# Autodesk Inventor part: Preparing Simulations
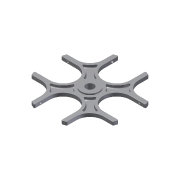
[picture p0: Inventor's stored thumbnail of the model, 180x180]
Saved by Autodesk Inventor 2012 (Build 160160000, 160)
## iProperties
Created: 2004-06
Part Number: Preparing Simulations
Document SubType Name: Modeling
Designer: brent
Manufacturer: Standard
Standards Organization: Custom
Density: 1 g/cm^3
Material: Default
Mass: 73.4254 g
Surface Area: 338.43 cm^2
Volume: 73.4254 cm^3
Author: Autodesk, Inc.
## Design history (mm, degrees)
sketch "Sketch1"
  geometry: C1 r 100 at (0, 0)
  constraints: 1 centre point
  dimensions: "d0" = 200 diameter of C1
extrude "Extrusion1" new body sketch "Sketch1" stored distance "d1" = 8; taper "d2" = 0 deg
sketch "Sketch2"
  geometry: L1 (-30, 95.394)-(-30, 60.394); L2 (30, 60.394)-(30, 95.394); A1 r 100 centre (0, 0) between (-30, 95.394) and (30, 95.394) reference; A2 r 30 centre (0, 60.394) between (-30, 60.394) and (30, 60.394)
  constraints: 4 end point, 4 point on circle, 2 tangent, 1 centre point, 1 parallel, 1 vertical, 1 vertical alignment
  dimensions: "d3" = 60 distance between parallel lines of L2 L1; "d4" = 35 distance of L2.start L2.end
extrude "Extrusion2" cut sketch "Sketch2" stored distance "d5" = 8; taper "d6" = 0 deg
sketch "Sketch5"
  geometry: L1 (0, 35)-(8, 35) reference; L2 (0, 0)-(8, 0) reference; L3 (0, -30.394)-(0, 35) reference; 2 further points
  constraints: 1 midpoint, 1 vertical alignment
  dimensions: "d30" = 20 distance from line of L2 point (4, 20)
hole "Hole2" sketch "Sketch5" at (4, 20) diameter "d31" = 5; stored, may be unused: countersink angle "d35" = 90 deg, drill point angle "d37" = 118 deg; dims "d32" = 6, "d33" = 4, "d34" = 2, "d36" = 5
mirror "Mirror1"
pattern_circular "Circular Pattern2" dims "d39" = 360 deg
sketch "Sketch7"
  geometry: L1 (-30, 60.394)-(-30, 95.394) reference; L2 (-95.394, 30)-(-60.394, 30) reference; L3 (-40, 91.652)-(-40, 70); L4 (-70, 40)-(-91.652, 40); A1 r 100 centre (0, 0) between (-30, 95.394) and (-95.394, 30) reference; A2 r 30 centre (-70, 70) between (-70, 40) and (-40, 70)
  constraints: 4 end point, 4 point on circle, 2 tangent, 1 centre point
  dimensions: "d41" = 10 distance between parallel lines of L1 L3 (= d42); "d42" = 10 distance between parallel lines of L2 L4; "d43" = 30 radius of A2
extrude "Extrusion5" cut sketch "Sketch7" stored distance "d44" = 6; taper "d45" = 0 deg
pattern_circular "Circular Pattern3" dims angle "d47" = 360 deg
sketch "Sketch4"
  geometry: C1 r 20 at (0, 0); A1 r 100 centre (0, 0) between (95.394, 30) and (30, 95.394) reference
  constraints: 1 centre point, 1 coincident
  dimensions: "d13" = 40 diameter of C1
extrude "Extrusion4" join sketch "Sketch4" stored distance "d14" = 14; taper "d15" = 0 deg
hole "Hole1" diameter "d18" = 18; stored, may be unused: countersink angle "d22" = 90 deg, drill point angle "d24" = 118 deg; dims "d16" = 10, "d17" = 10, "d19" = 6, "d20" = 4, "d21" = 2, "d23" = 8
sketch "Sketch8"
  geometry: C1 r 20 at (0, 0) reference; A1 r 30 centre (0, 60.394) between (-30, 60.394) and (30, 60.394) reference; A2 r 30 centre (-70, 70) between (-70, 40) and (-40, 70) reference; A3 r 30 centre (-60.394, 0) between (-60.394, -30) and (-60.394, 30) reference; A4 r 100 centre (0, 0) between (95.394, 30) and (91.652, 40) reference; A5 r 36 centre (0, 60.394) between (-35.941, 58.338) and (-6.913, 25.064); A6 r 36 centre (-70, 70) between (-58.338, 35.941) and (-35.941, 58.338); A7 r 36 centre (-60.394, 0) between (-25.064, 6.913) and (-58.338, 35.941); A8 r 26 centre (0, 0) between (-25.064, 6.913) and (-6.913, 25.064)
  constraints: 8 point on circle, 4 centre point, 3 coincident, 1 concentric
  dimensions: "d49" = 6 radial gap between concentric circles of A5 A1; "d50" = 6 radial gap between concentric circles of A2 A6 (= d49); "d51" = 6 radial gap between concentric circles of A3 A7 (= d49); "d52" = 6 radial gap between concentric circles of A8 C1 (= d49)
extrude "Extrusion6" cut sketch "Sketch8" distance "d53" = 6; taper "d54" = 0 deg
fillet "Fillet1" dims "d55" = 2
pattern_circular "Circular Pattern4" dims angle "d57" = 360 deg
fillet "Fillet3" dims "d60" = 2
fillet "Fillet2" dims "d59" = 0.5
body "Solid1"
